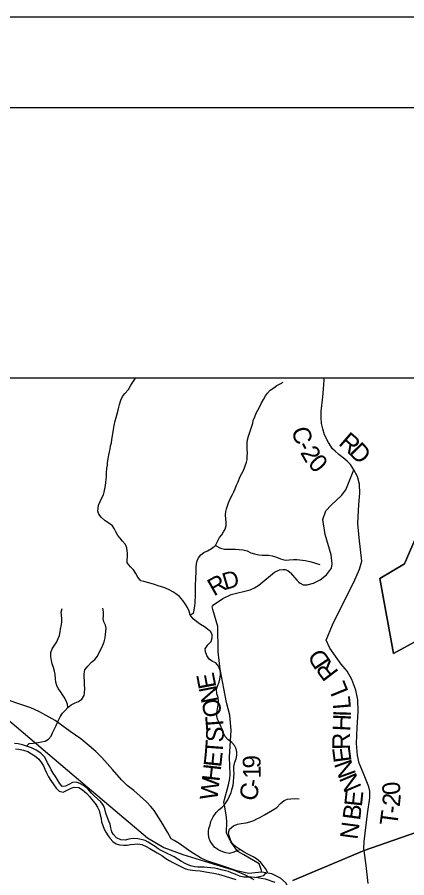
# Model space of a CAD drawing. Extents: x -139 to 835, y 0 to 440.
# Drawn here: x 419.7 to 462.8, y 344.8 to 440 of the extents above; entities that cross this region are included whole.
import ezdxf

# ---------------------------------------------------------------- set-up
doc = ezdxf.new("R2010")
doc.units = 0
for name, color, linetype in [('Default', 7, 'Continuous'), ('GM_X_County_Road', 7, 'Continuous'), ('GM_X_County_Road_Text', 7, 'Continuous'), ('GM_X_Minor_River', 7, 'Continuous'), ('GM_X_Rail_Line', 7, 'Continuous'), ('GM_X_State_Route', 7, 'Continuous'), ('GM_X_Township_Road', 7, 'Continuous'), ('GM_X_Township_Road_Text', 7, 'Continuous'), ('SH_Border', 7, 'Continuous'), ('SH_Cut_Line', 7, 'Continuous')]:
    doc.layers.add(name, color=color, linetype=linetype)

msp = doc.modelspace()

# ---------------------------------------------------------------- linework, layer by layer
at = {"layer": 'Default'}
for points in [[(567.097, 400.079), (373.24, 400.079), (373.24, 306.128)], [(463.652, 370.95), (461.283, 369.652), (459.766, 377.922), (462.506, 379.576), (465.334, 386.174)], [(465.334, 386.174), (462.506, 379.576), (459.766, 377.922), (461.283, 369.652), (463.652, 370.95)], [(450.155, 344.542), (458.032, 347.876), (477.617, 354.671)], [(477.617, 354.671), (458.032, 347.876), (450.155, 344.542)]]:
    msp.add_lwpolyline(points, dxfattribs=at)
at = {"layer": 'GM_X_County_Road'}
for points in [[(456.888, 389.958), (456.535, 390.524), (456.173, 390.898), (455.745, 391.263), (455.24, 391.655), (454.825, 392.019), (454.563, 392.281), (454.124, 392.971), (453.666, 393.817), (453.474, 394.474), (453.318, 395.068), (453.283, 395.73), (453.288, 396.415), (453.479, 398.018), (453.569, 398.856), (453.618, 399.911), (453.594, 400.079)], [(446.736, 345.459), (446.68, 345.769), (446.459, 346.371), (444.732, 347.388), (444.079, 347.753), (443.307, 348.825), (442.842, 349.775), (442.874, 351.104), (442.806, 351.788), (442.604, 352.877), (442.552, 353.164), (442.604, 353.506), (443.069, 355.126), (443.205, 355.839), (443.231, 356.268), (443.148, 358.194), (443.35, 361.154), (443.219, 362.828), (442.839, 364.222), (442.132, 367.922), (441.893, 369.833), (441.868, 372.635), (441.304, 374.515), (441.258, 374.8), (441.291, 374.88), (441.403, 375.026), (442.433, 375.736), (443.354, 376.169), (445.464, 376.675), (445.919, 376.896), (446.394, 377.199), (448.144, 378.625), (448.687, 378.904), (449.087, 378.943), (449.325, 378.917), (449.595, 378.824), (449.821, 378.652), (449.912, 378.575), (450.594, 377.736), (450.809, 377.519), (450.961, 377.425), (451.319, 377.253), (451.731, 377.22), (452.445, 377.405), (453.192, 377.798), (453.903, 378.359), (454.424, 379.094), (454.503, 379.564), (454.4, 380.537), (453.72, 382.79), (453.485, 384.448), (453.805, 385.428), (454.406, 386.049), (455.545, 387.116), (456.034, 387.743), (456.888, 389.958)]]:
    msp.add_lwpolyline(points, dxfattribs=at)
at = {"layer": 'GM_X_Minor_River'}
for points in [[(431.882, 380.704), (431.823, 381.316), (431.657, 381.702), (431.321, 382.076), (431.063, 382.39), (430.818, 382.704), (430.613, 383.114), (430.421, 383.475), (430.241, 383.777), (429.839, 384.068), (429.423, 384.311), (428.983, 384.711), (428.725, 385.061), (428.624, 385.373), (428.64, 385.709), (428.67, 386.057), (428.856, 386.44), (429.016, 386.775), (429.229, 387.181), (429.311, 387.493), (429.393, 387.852), (429.449, 388.212), (429.478, 388.548), (429.534, 388.932), (429.563, 389.231), (429.58, 389.603), (429.624, 390.119), (429.666, 390.455), (429.696, 390.755), (429.752, 391.175), (429.835, 391.618), (429.89, 391.942), (429.958, 392.253), (430.014, 392.601), (430.109, 392.924), (430.165, 393.32), (430.275, 393.932), (430.358, 394.423), (430.428, 394.867), (430.538, 395.382), (430.633, 395.753), (430.741, 396.149), (430.85, 396.568), (430.931, 396.868), (431.013, 397.191), (431.161, 397.658), (431.348, 398.053), (431.612, 398.387), (431.995, 398.852), (432.208, 399.235), (432.407, 399.545), (432.632, 399.868), (432.768, 400.079)], [(438.804, 373.907), (439.185, 374.108), (439.267, 374.444), (439.336, 374.912), (439.365, 375.211), (439.382, 375.511), (439.398, 375.883), (439.415, 376.219), (439.418, 376.591), (439.41, 377.084), (439.413, 377.407), (439.429, 377.719), (439.447, 378.175), (439.463, 378.487), (439.466, 378.823), (439.469, 379.136), (439.512, 379.543), (439.594, 379.891), (439.728, 380.238), (439.992, 380.548), (440.334, 380.798), (440.741, 380.987), (441.162, 381.248), (441.609, 381.581), (441.809, 381.963), (442.062, 382.454), (442.3, 382.776), (442.512, 383.086), (442.685, 383.409), (442.793, 383.781), (442.81, 384.129), (442.775, 384.537), (442.726, 384.945), (442.743, 385.329), (442.825, 385.629), (442.932, 385.964), (443.053, 386.311), (443.24, 386.73), (443.48, 387.209), (443.627, 387.52), (443.787, 387.866), (443.922, 388.262), (444.121, 388.62), (444.322, 389.123), (444.535, 389.541), (444.708, 389.888), (445.044, 390.786), (445.099, 391.086), (445.128, 391.422), (445.145, 391.842), (445.122, 392.166), (445.113, 392.538), (445.117, 392.922), (445.159, 393.27), (445.268, 393.677), (445.362, 394.001), (445.483, 394.336), (445.591, 394.671), (445.739, 395.102), (445.794, 395.402), (445.968, 395.821), (446.129, 396.228), (446.289, 396.539), (446.502, 396.957), (446.675, 397.28), (446.914, 397.722), (447.127, 398.117), (447.352, 398.428), (447.669, 398.761), (448.051, 399.035), (448.406, 399.272), (448.747, 399.474), (449.089, 399.663)], [(441.609, 381.581), (442.168, 381.301), (442.611, 381.189), (443.017, 381.198), (443.356, 381.196), (443.839, 381.181), (444.244, 381.142), (444.675, 381.103), (445.105, 380.98), (445.508, 380.785), (445.925, 380.65), (446.407, 380.538), (446.773, 380.511), (447.125, 380.509), (447.491, 380.518), (447.896, 380.456), (448.364, 380.284), (448.794, 380.125), (449.315, 379.965), (449.772, 379.986), (450.243, 380.031), (450.596, 380.028), (450.935, 379.99), (451.523, 379.926), (452.044, 379.826), (452.435, 379.715), (452.774, 379.605), (453.152, 379.482)], [(444.392, 347.918), (444.039, 347.873), (443.645, 347.672), (443.173, 347.519), (442.769, 347.594), (442.417, 347.716), (441.988, 347.899), (441.533, 348.191), (441.275, 348.517), (441.017, 348.89), (440.929, 349.191), (440.841, 349.6), (440.858, 349.996), (440.887, 350.308), (441.009, 350.715), (441.104, 351.05), (441.344, 351.589), (441.701, 352.066), (442.005, 352.376), (442.36, 352.662), (442.703, 353.019), (442.995, 353.449), (443.182, 353.856), (443.343, 354.263), (443.424, 354.586), (443.573, 355.089), (443.589, 355.425), (443.634, 356.013), (443.663, 356.337), (443.654, 356.769), (443.658, 357.165), (443.767, 357.632), (443.888, 358.004), (443.958, 358.387), (443.961, 358.747), (443.899, 359.096), (443.707, 359.469), (443.423, 359.807), (442.994, 360.122), (442.684, 360.449), (442.491, 360.786), (442.352, 361.243), (442.173, 361.664), (441.981, 362.074), (441.841, 362.387), (441.766, 362.76), (441.769, 363.096), (441.825, 363.515), (441.908, 363.983), (441.951, 364.331), (441.903, 364.775), (441.776, 365.196), (441.716, 365.712), (441.85, 366.036), (442.024, 366.466), (442.105, 366.79), (442.175, 367.269), (442.165, 367.57), (442.09, 367.87), (441.963, 368.243), (441.64, 368.618), (441.302, 368.776), (440.912, 369.007), (440.642, 369.429), (440.528, 369.814), (440.492, 370.15), (440.784, 370.604), (441.153, 370.974), (441.262, 371.393), (441.239, 371.693), (441.111, 372.03), (440.722, 372.345), (440.385, 372.599), (439.943, 372.855), (439.567, 373.133), (439.152, 373.461), (438.804, 373.907), (438.691, 374.316), (438.538, 374.725), (438.281, 375.147), (438.023, 375.497), (437.622, 375.932), (437.246, 376.259), (436.909, 376.465), (436.571, 376.636), (436.012, 376.904), (435.647, 377.003), (435.269, 377.126), (434.892, 377.26), (434.488, 377.383), (434.097, 377.482), (433.706, 377.593), (433.368, 377.692), (433.032, 378.102), (432.827, 378.476), (432.557, 378.91), (432.233, 379.213), (431.846, 379.672), (431.836, 379.984), (431.879, 380.319), (431.882, 380.704)], [(420.745, 359.412), (421.009, 359.698), (421.505, 359.73), (421.976, 359.798), (422.394, 359.867), (422.774, 359.948), (423.167, 360.161), (423.458, 360.518), (423.592, 360.866), (423.805, 361.296), (424.005, 361.667), (424.272, 362.277), (424.458, 362.659), (424.723, 363.041), (424.987, 363.351), (425.291, 363.661), (425.672, 363.958), (426.105, 364.171), (426.473, 364.348), (426.854, 364.597), (427.093, 365.004), (427.135, 365.303), (427.165, 365.771), (427.156, 366.167), (427.135, 366.624), (427.099, 367.044), (427.09, 367.392), (427.185, 367.824), (427.503, 368.241), (427.925, 368.67), (428.294, 368.979), (428.558, 369.35), (428.811, 369.816), (429.024, 370.246), (429.158, 370.569), (429.305, 370.916), (429.414, 371.36), (429.444, 371.743), (429.499, 372.079), (429.515, 372.391), (429.441, 372.788), (429.288, 373.149), (429.212, 373.462), (429.229, 373.81), (429.22, 374.266), (429.146, 374.674)], [(425.291, 363.661), (425.268, 364.045), (425.064, 364.491), (424.884, 364.816), (424.665, 365.142), (424.486, 365.456), (424.228, 365.77), (424.074, 366.119), (423.986, 366.48), (423.938, 366.852), (423.89, 367.309), (423.815, 367.681), (423.715, 368.09), (423.575, 368.512), (423.487, 368.86), (423.413, 369.305), (423.418, 369.749), (423.578, 370.144), (423.79, 370.478), (424.069, 370.932), (424.229, 371.303), (424.376, 371.65), (424.458, 372.034), (424.501, 372.333), (424.61, 372.849), (424.639, 373.161), (424.616, 373.473), (424.581, 373.869), (424.571, 374.205), (424.667, 374.637)], [(445.956, 344.871), (445.565, 344.922), (445.094, 344.913), (444.755, 344.903), (444.259, 345.027), (443.804, 345.246), (443.401, 345.405), (443.062, 345.527), (442.71, 345.614), (442.254, 345.737), (441.863, 345.824), (441.524, 345.898), (441.054, 345.962), (440.689, 345.988), (440.349, 346.003), (440.023, 346.005), (439.67, 346.02), (439.318, 346.058), (438.848, 346.182), (438.341, 346.389), (437.873, 346.657), (437.458, 346.912), (437.055, 347.167), (436.678, 347.349), (436.34, 347.496), (435.963, 347.667), (435.625, 347.849), (435.287, 348.056), (434.937, 348.286), (434.586, 348.529), (434.171, 348.796), (433.833, 348.954), (433.39, 349.078), (433.025, 349.14), (432.516, 349.18), (432.032, 349.1), (431.639, 349.006), (431.143, 349.022), (430.688, 349.253), (430.339, 349.616), (430.146, 349.918), (430.045, 350.35), (429.958, 350.759), (429.818, 351.096), (429.652, 351.566), (429.513, 351.987), (429.374, 352.468), (429.234, 352.853), (428.937, 353.239), (428.575, 353.566), (428.199, 353.905), (427.902, 354.207), (427.501, 354.666), (427.035, 355.03), (426.697, 355.236), (426.255, 355.42), (425.811, 355.387), (425.404, 355.162), (425.05, 354.985), (424.683, 354.94), (424.387, 355.29), (424.104, 355.737), (423.924, 356.05), (423.679, 356.4), (423.461, 356.798), (423.256, 357.195), (423.064, 357.569), (422.897, 357.882), (422.705, 358.232), (422.304, 358.631), (421.785, 358.971), (421.292, 359.227), (420.745, 359.412), (420.29, 359.547), (419.795, 359.659), (419.403, 359.686)], [(419.515, 359.109), (419.867, 359.071), (420.414, 358.958), (420.87, 358.822), (421.285, 358.531), (421.648, 358.312), (422.088, 357.949), (422.398, 357.562), (422.59, 357.213), (422.757, 356.839), (422.987, 356.369), (423.153, 356.02), (423.41, 355.598), (423.732, 355.127), (424.016, 354.765), (424.326, 354.427), (424.769, 354.315), (425.215, 354.528), (425.674, 354.764), (426.001, 354.846), (426.497, 354.818), (426.926, 354.551), (427.405, 354.151), (427.676, 353.849), (427.921, 353.523), (428.309, 353.064), (428.592, 352.642), (428.745, 352.28), (428.884, 351.787), (428.972, 351.415), (429.033, 351.042), (429.147, 350.633), (429.3, 350.224), (429.492, 349.886), (429.75, 349.477), (429.969, 349.175), (430.266, 348.861), (430.629, 348.606), (430.994, 348.483), (431.437, 348.444), (431.869, 348.465), (432.235, 348.51), (432.68, 348.567), (433.019, 348.6), (433.489, 348.513), (433.97, 348.317), (434.347, 348.098), (435.152, 347.588), (435.698, 347.296), (436.139, 346.993), (436.49, 346.763), (436.97, 346.507), (437.412, 346.264), (437.841, 346.045), (438.232, 345.886), (438.57, 345.775), (439.066, 345.7), (439.405, 345.661), (439.94, 345.598), (440.527, 345.509), (440.958, 345.434), (441.44, 345.347), (441.936, 345.235), (442.327, 345.137), (442.679, 345.038), (443.851, 344.67)], [(445.956, 344.871), (446.966, 345.086), (447.147, 345.303), (447.36, 345.461), (447.129, 345.859), (446.897, 346.196), (446.639, 346.522), (446.133, 346.934), (445.782, 347.152), (445.106, 347.493), (444.768, 347.688), (444.392, 347.918), (443.925, 348.246), (443.471, 348.657), (443.279, 349.03), (443.126, 349.476), (443.038, 349.812), (443.173, 350.219), (443.595, 350.6), (444.041, 350.777), (444.459, 350.858), (445.022, 350.926), (445.415, 351.02), (445.848, 351.185), (446.176, 351.35), (446.53, 351.516), (447.016, 351.788), (447.91, 352.31), (448.383, 352.631), (448.806, 353.048), (449.214, 353.381), (449.568, 353.535), (449.935, 353.592), (450.327, 353.601), (450.862, 353.586)], [(448.201, 344.31), (447.144, 344.682), (446.648, 344.782), (446.309, 344.82), (445.956, 344.871)]]:
    msp.add_lwpolyline(points, dxfattribs=at)
at = {"layer": 'GM_X_Rail_Line'}
msp.add_lwpolyline([(395.652, 400.079), (399.415, 391.692), (399.8, 390.495), (400.096, 389.074), (400.426, 386.818), (400.526, 385.009), (401.002, 383.465), (401.506, 382.312), (402.853, 380.012), (407.3, 372.714), (408.705, 371.009), (410.068, 369.65), (412.003, 367.98), (426.013, 356.104), (434.107, 349.279), (435.89, 348.177), (437.988, 347.404), (441.359, 346.369), (443.681, 345.681), (444.906, 345.179), (445.837, 344.639)], dxfattribs=at)
at = {"layer": 'GM_X_State_Route'}
for points in [[(446.736, 345.459), (445.269, 345.323), (443.979, 345.607), (442.129, 346.255), (440.657, 346.733), (439.968, 347.061), (438.876, 347.716), (437.604, 348.649), (437.045, 348.953), (436.733, 349.159), (436.309, 349.906), (435.626, 351.051), (434.827, 352.28), (434.452, 352.739), (433.973, 353.234), (432.586, 354.48), (431.859, 355.037), (431.225, 355.665), (430.242, 356.812), (429.039, 358.129), (428.392, 358.817), (427.666, 359.447), (426.745, 360.209), (425.538, 361.022), (423.891, 362.234), (422.891, 362.805), (422.098, 363.243), (421.201, 363.645), (420.095, 364.014), (418.468, 364.554)], [(461.936, 318.695), (461.787, 319.53), (461.653, 321.204), (460.72, 322.248), (459.959, 323.239), (459.079, 324.531), (458.741, 325.026), (457.98, 327.702), (457.828, 328.148), (457.128, 328.986), (455.915, 330.436), (455.682, 330.714), (455.08, 333.568), (454.648, 334.227), (452.306, 334.994), (450.539, 336.505), (449.794, 343.483), (449.431, 344.255), (448.803, 344.8), (447.829, 345.277), (446.736, 345.459)]]:
    msp.add_lwpolyline(points, dxfattribs=at)
at = {"layer": 'GM_X_Township_Road'}
msp.add_lwpolyline([(458.49, 344.221), (458.286, 346.201), (458.04, 347.859), (458.026, 348.003), (458.042, 348.867), (458.423, 351.921), (458.679, 353.693), (458.689, 354.426), (458.555, 354.915), (457.984, 356.379), (457.498, 357.504), (457.303, 358.365), (457.198, 359.675), (457.285, 361.472), (457.377, 363.201), (457.346, 364.522), (457.123, 365.575), (456.667, 366.763), (456.155, 367.682), (455.522, 368.465), (454.861, 369.345), (454.266, 370.225), (453.85, 371.136), (454.561, 372.814), (455.888, 375.502), (456.889, 377.529), (457.543, 378.975), (457.776, 379.866), (457.498, 382.442), (457.338, 384.005), (457.453, 386.123), (457.575, 387.364), (457.529, 388.373), (457.3, 389.207), (456.888, 389.958)], dxfattribs=at)
at = {"layer": 'SH_Border'}
msp.add_lwpolyline([(30, 430), (670, 430), (670, 10), (30, 10)], close=True, dxfattribs=at)
at = {"layer": 'SH_Cut_Line'}
for points in [[(0, 0), (680, 0), (680, 440), (0, 440)], [(607.596, 213.413), (607.596, 400.079), (373.24, 400.079), (373.24, 228.621), (390.412, 227.867), (402.968, 227.036), (407.389, 226.858), (433.728, 225.419), (479.461, 222.215), (494.743, 221.147), (512.652, 220.106), (533.705, 218.461), (553.865, 217.083)]]:
    msp.add_lwpolyline(points, close=True, dxfattribs=at)

# ---------------------------------------------------------------- texts
at = {"layer": 'GM_X_County_Road_Text'}
for s, height, rotation, p in [('C', 1.966, 284.66522, (450.014, 394.433)), ('R', 1.973, 319.00508, (455.115, 392.786)), ('D', 1.981, 314.27722, (456.253, 391.799)), ('2', 1.982, 300.28856, (450.934, 391.865)), ('-', 1.98, 297.70767, (450.543, 392.605)), ('0', 1.984, 311.97534, (451.739, 390.568)), ('D', 1.856, 16.56183, (442.699, 376.659)), ('R', 1.93, 29.29966, (441.437, 375.936)), ('E', 1.963, 100.80602, (441.728, 365.934)), ('N', 1.963, 101.08271, (442.033, 364.38)), ('O', 1.965, 103.58661, (442.402, 362.856)), ('T', 1.959, 94.50074, (442.552, 361.232)), ('S', 1.959, 86.96607, (442.491, 359.785)), ('T', 1.959, 85.64661, (442.387, 358.403)), ('E', 1.96, 84.00435, (442.241, 357.014)), ('9', 1.958, 92.02972, (446.617, 356.982)), ('H', 1.96, 83.37358, (442.057, 355.422)), ('1', 1.958, 90.04988, (446.619, 355.813)), ('W', 1.96, 83.35162, (441.815, 353.352)), ('C', 1.966, 75.58198, (446.06, 353.198)), ('-', 1.962, 79.64423, (446.457, 354.76))]:
    msp.add_text(s, height=height, rotation=rotation, dxfattribs=at).set_placement(p)
at = {"layer": 'GM_X_Township_Road_Text'}
for s, height, rotation, p in [('D', 1.984, 123.64383, (454.388, 368.781)), ('R', 1.985, 127.42461, (455.294, 367.599)), ('L', 1.974, 111.9603, (456.356, 365.42)), ('L', 1.959, 94.88843, (456.594, 363.562)), ('H', 1.958, 87.27565, (456.501, 361.01)), ('I', 1.958, 88.25539, (456.578, 362.62)), ('R', 1.958, 90.59563, (456.492, 359.007)), ('E', 1.96, 97.52771, (456.664, 357.726)), ('N', 1.971, 109.71765, (457.181, 356.315)), ('N', 1.975, 112.94955, (457.795, 354.865)), ('0', 1.959, 95.45717, (462.084, 354.103)), ('E', 1.96, 83.83958, (457.783, 352.64)), ('2', 1.96, 84.23636, (461.972, 352.65)), ('B', 1.96, 82.47667, (457.585, 351.133)), ('T', 1.96, 82.41161, (461.693, 350.526)), ('-', 1.96, 82.70146, (461.872, 351.869)), ('N', 1.96, 82.45235, (457.304, 349.013))]:
    msp.add_text(s, height=height, rotation=rotation, dxfattribs=at).set_placement(p)

doc.saveas('drawing.dxf')
